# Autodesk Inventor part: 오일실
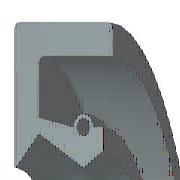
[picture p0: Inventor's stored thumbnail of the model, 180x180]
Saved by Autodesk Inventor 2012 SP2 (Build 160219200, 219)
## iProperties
IsCustomPart: 0
Created: 2009-02
Part Number: 오일실
Material: 고무
Description: 오일-실
Document SubType Name: Modeling
Standard: KS B 2804
Designer: KYOUNG IL JANG
Standards Organization: KS
Language: ko-KR
Size Designation: D - 20 32 8
Categories: <MemberInstance><Categories><Category DisplayName="샤프트 부품" InternalName="7f7aeb1f-a693-4053-b835-cee3144e0d98" Mnemonic="SHFT"><Category DisplayName="실링" Intern
Density: 0.93 g/cm^3
Mass: 2.19344 g
Surface Area: 31.4782 cm^2
Volume: 2.35853 cm^3
Author: KYOUNG IL JANG
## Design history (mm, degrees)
revolve "본체" stored, may be unused: angle "d17" = 90 deg
revolve "스프링1" stored, may be unused: angle "d18" = 90 deg
body "Solid1"
sketch "스케치1"
  geometry: L1 (0, 16)-(8, 16); L2 (8, 14.25)-(1.75, 14.25); L3 (1.75, 11.75)-(4.9, 10); L4 (4.9, 10)-(0, 10); L5 (0, 0)-(9.586, 0) reference; L6 (4.9, 10)-(6.3, 10.875); L7 (0, 18)-(0, -3) reference; L8 (-1.941, 0)-(11.507, 0) reference; L9 (4.2, 12.1)-(1.75, 12.71); L10 (1.75, 12.71)-(1.75, 14.25); L11 (0, 16)-(0, 10.088); L12 (4.9, 10)-(0, 10); L13 (1.75, 11.75)-(0.152, 10.028); L14 (8, 16)-(8, 14.25); L15 (5.6, 12.1)-(6.3, 12.1); L16 (6.3, 12.1)-(6.3, 10.875); C1 r 0.455 at (4.9, 12.1); A1 r 0.7 centre (4.9, 12.1) between (5.6, 12.1) and (4.2, 12.1); A2 r 0.088 centre (0.088, 10.088) between (0, 10.088) and (0.152, 10.028); 1 further point
  constraints: 28 end point, 5 horizontal alignment, 5 point on line, 4 point on circle, 4 vertical alignment, 3 centre point, 3 tangent, 2 collinear, 2 horizontal, 2 perpendicular, 1 coincident, 1 parallel
  dimensions: "d0" = 32 diameter of L1 L5 (= SD2); "d1" = 1.75 distance of L1.end L2.start (= SD); "d2" = 0.91 diameter of C1 (= SPDI); "d3" = 1.4 diameter of A1 (= SPDA); "d4" = 20 diameter of L3.end L5 (= NND); "d5" = 23.5 diameter of L3.start L5 (= TKDM); "d7" = 25.42 diameter of L9.end L5 (= TKDM + 0.24 x SWDT); "d8" = 1.75 distance between parallel lines of L11 L10 (= SD); "d9" = 4.9 distance from line of L11 C1.centre (= SPDST); "d10" = 24.2 diameter of C1.centre L5 (= HLDM); "d11" = 0.0875 radius of A2 (= 0.25 x LAB); "d12" = 6.3 distance between parallel lines of L11 L16 (= SDI); "d13" = 21.75 diameter of L6.end L5 (= ABDM); "d14" = 8 distance from line of L11 L1.end (= SWDT)
fillet "모깎기1" dims "d6" = 0.3 (= RR)
other parameters: "SD2" = 32 [user parameter; used in 1 equation term], "SWDT" = 8 [user parameter; used in 2 equation terms], "RR" = 0.3 [user parameter; used in 1 equation term], "SD" = 1.75 [user parameter; used in 2 equation terms], "NND" = 20 [user parameter; used in 1 equation term], "SPDA" = 1.4 [user parameter; used in 1 equation term], "SPDI" = 0.91 [user parameter; used in 1 equation term], "TKDM" = 23.5 [user parameter; used in 2 equation terms], "HLDM" = 24.2 [user parameter; used in 1 equation term], "ABDM" = 21.75 [user parameter; used in 1 equation term], "SDI" = 6.3 [user parameter; used in 1 equation term], "SPDST" = 4.9 [user parameter; used in 1 equation term], "LAB" = 0.35 [user parameter; used in 1 equation term], "d15" = 0, "d16" = 0, "d19" = 0
